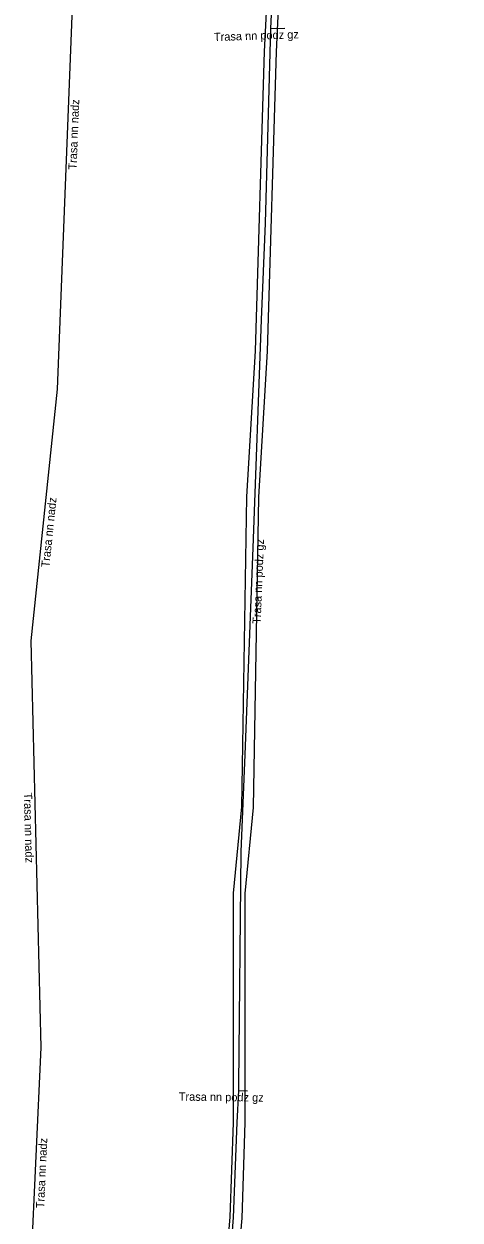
# Model space of a CAD drawing. Extents: x -747038 to -746494, y -1019526 to -1019195.
# Drawn here: x -746719.8 to -746693.3, y -1019358.2 to -1019285.5 of the extents above; entities that cross this region are included whole.
import ezdxf

# ---------------------------------------------------------------- set-up
doc = ezdxf.new("R2010")
doc.units = 0
for name, color, linetype in [('Popiskový text - Ostatní atributy Trasy', 7, 'Continuous'), ('Spojnice NN', 7, 'Continuous'), ('Spojnice VN', 7, 'Continuous')]:
    doc.layers.add(name, color=color, linetype=linetype)

msp = doc.modelspace()

# ---------------------------------------------------------------- linework, layer by layer
at = {"layer": 'Spojnice NN'}
for points in [[(-746703.361, -1019252.797), (-746703.487, -1019253.723), (-746703.856, -1019266.76), (-746704.206, -1019272.736), (-746704.83, -1019285.79)], [(-746716.5, -1019274.7), (-746717.8, -1019307.7)], [(-746704.83, -1019285.79), (-746705.161, -1019297.607), (-746705.395, -1019303.494), (-746705.903, -1019317.344), (-746706.407, -1019329.894), (-746706.645, -1019335.813), (-746706.786, -1019349.946), (-746706.79, -1019350.32)], [(-746704.83, -1019285.79), (-746703.97, -1019285.761)], [(-746717.8, -1019307.7), (-746719.4, -1019323)], [(-746719.4, -1019323), (-746718.8, -1019347.7)], [(-746718.8, -1019347.7), (-746719.4, -1019360.9)], [(-746706.79, -1019350.32), (-746706.877, -1019352.251), (-746707.098, -1019358.031), (-746707.573, -1019364.229), (-746707.736, -1019370.196), (-746708.114, -1019380.162), (-746708.612, -1019390.39), (-746708.633, -1019390.809)], [(-746706.79, -1019350.32), (-746706.242, -1019350.327)]]:
    msp.add_lwpolyline(points, dxfattribs=at)
at = {"layer": 'Spojnice VN'}
for points in [[(-746707.88, -1019364.864), (-746707.283, -1019358.015), (-746707.091, -1019352.25), (-746707.093, -1019338.314), (-746706.586, -1019333.082), (-746706.272, -1019314.239), (-746705.742, -1019305.366), (-746705.202, -1019287.185), (-746704.049, -1019264.456), (-746703.818, -1019252.199), (-746702.137, -1019250.9), (-746693.317, -1019251.009)], [(-746693.345, -1019251.709), (-746701.901, -1019251.602), (-746703.124, -1019252.547), (-746703.349, -1019264.484), (-746703.732, -1019270.645), (-746704.502, -1019287.211), (-746705.042, -1019305.398), (-746705.572, -1019314.265), (-746705.886, -1019333.122), (-746706.393, -1019338.348), (-746706.391, -1019352.262), (-746706.585, -1019358.057), (-746707.182, -1019364.908)]]:
    msp.add_lwpolyline(points, dxfattribs=at)

# ---------------------------------------------------------------- texts
at = {"layer": 'Popiskový text - Ostatní atributy Trasy'}
for s, rotation, p in [('Trasa nn podz gz', 1.93134, (-746708.27, -1019286.556)), ('Trasa nn nadz', 87.74406, (-746716.624, -1019294.371)), ('Trasa nn nadz', 84.02998, (-746718.281, -1019318.549)), ('Trasa nn podz gz', 87.70027, (-746705.438, -1019321.97)), ('Trasa nn nadz', 271.39153, (-746719.826, -1019332.219)), ('Trasa nn podz gz', 359.26816, (-746710.418, -1019350.923)), ('Trasa nn nadz', 87.39744, (-746718.593, -1019357.474))]:
    msp.add_text(s, height=0.5, rotation=rotation, dxfattribs=at).set_placement(p)

doc.saveas('drawing.dxf')
